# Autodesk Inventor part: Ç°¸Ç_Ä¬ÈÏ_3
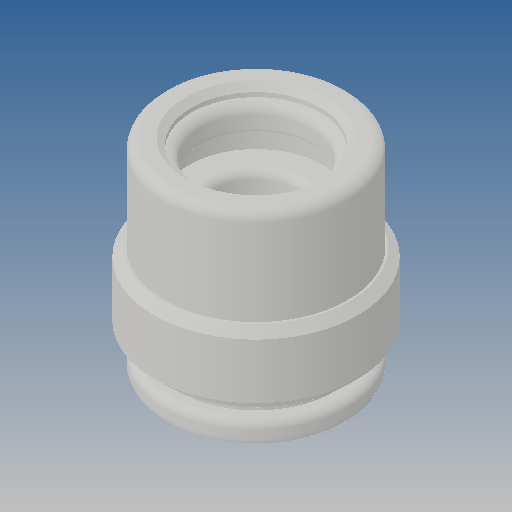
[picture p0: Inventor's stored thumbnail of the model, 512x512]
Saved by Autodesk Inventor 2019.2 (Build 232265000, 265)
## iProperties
Created: 2013-03
Part Number: Ç°¸Ç_Ä¬ÈÏ_3
Material: Ogólny
Document SubType Name: Modeling
Designer: CADENGINEERING4
Density: 1 g/cm^3
Appearance: Domyślna
Author: CADENGINEERING4
Revision Number: ÈÎºÎ
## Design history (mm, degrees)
feature "NONE"
node "Bryła1"
